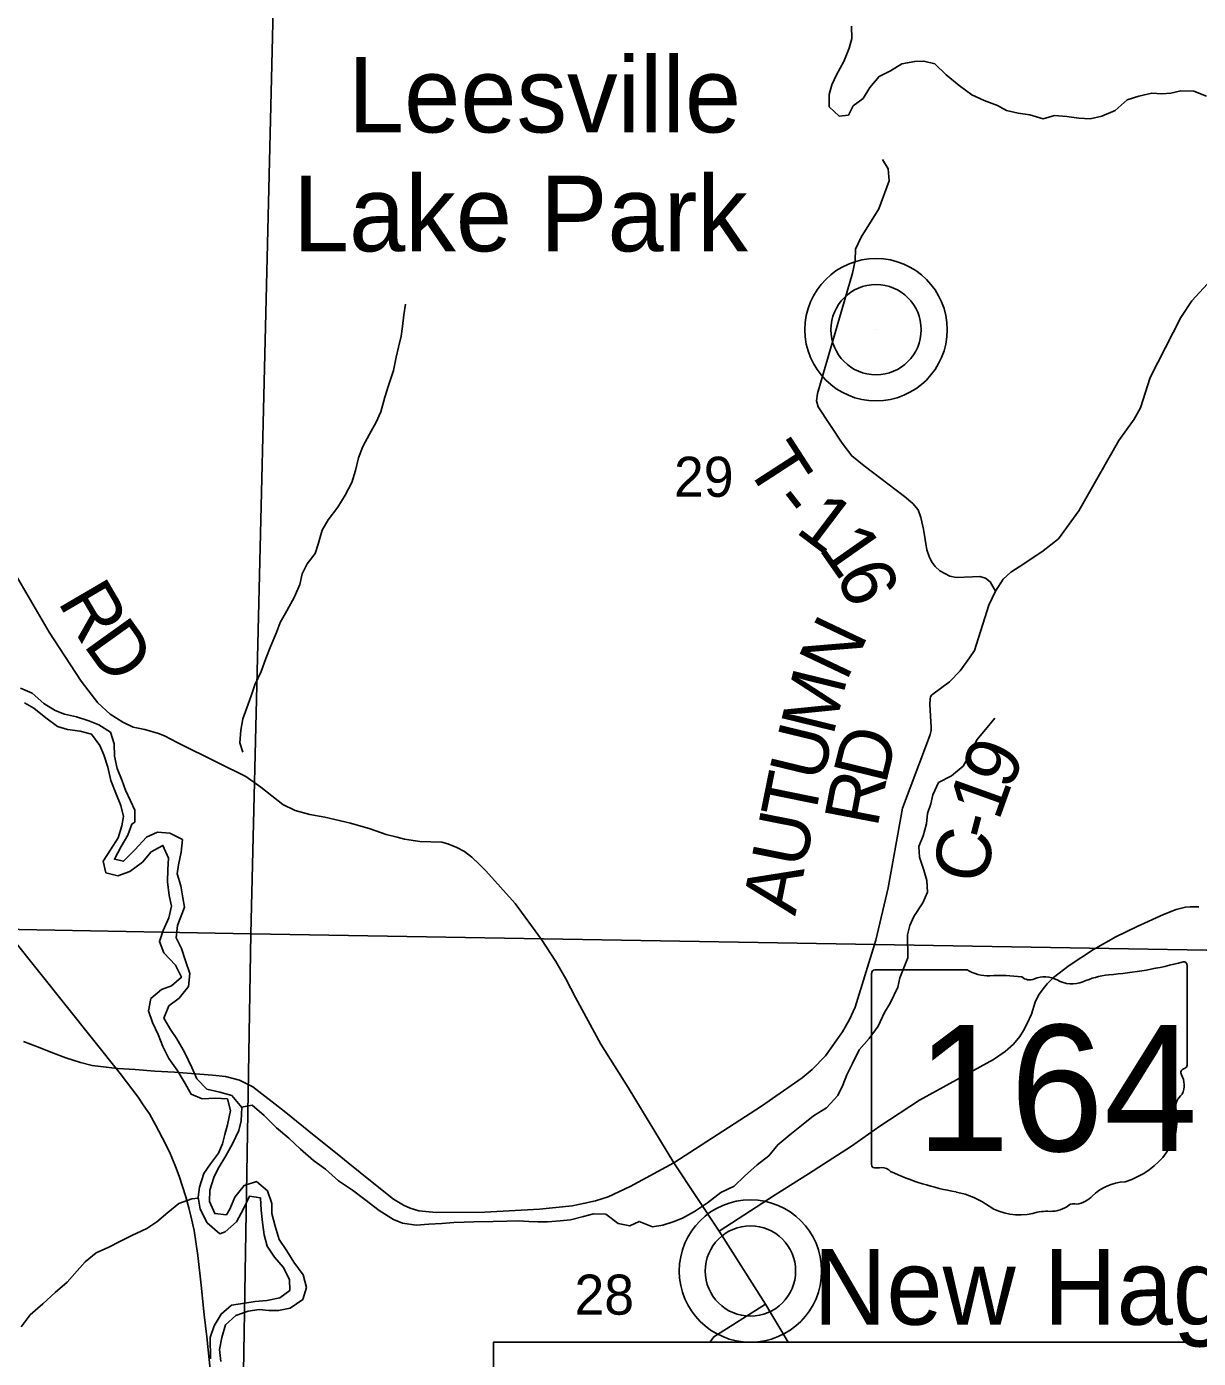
# Model space of a CAD drawing. Extents: x -1.2 to 34, y -8.5 to 22.
# Drawn here: x 6.085 to 7.31, y 18.307 to 19.699 of the extents above; entities that cross this region are included whole.
import ezdxf

# ---------------------------------------------------------------- set-up
doc = ezdxf.new("R2010")
doc.units = 0
for name, color, linetype in [('GM_X_County_Road', 7, 'Continuous'), ('GM_X_County_Road_Text', 7, 'Continuous'), ('GM_X_Major_Lake', 7, 'Continuous'), ('GM_X_Major_River', 7, 'Continuous'), ('GM_X_Minor_River', 7, 'Continuous'), ('GM_X_Rail_Line', 7, 'Continuous'), ('GM_X_Section', 7, 'Continuous'), ('GM_X_Section_Text', 7, 'Continuous'), ('GM_X_State_Location', 7, 'Continuous'), ('GM_X_State_Route', 7, 'Continuous'), ('GM_X_State_Shield', 7, 'Continuous'), ('GM_X_Township_Road', 7, 'Continuous'), ('GM_X_Township_Road_Text', 7, 'Continuous'), ('GM_X_Unincorporated', 7, 'Continuous'), ('GM_X_Unincorporated_Location', 7, 'Continuous'), ('GM_X_Unincorporated_Text', 7, 'Continuous'), ('SH_Text', 7, 'Continuous')]:
    doc.layers.add(name, color=color, linetype=linetype)

msp = doc.modelspace()

# ---------------------------------------------------------------- linework, layer by layer
at = {"layer": 'GM_X_County_Road'}
msp.add_line((6.8089, 18.4404), (6.7615, 18.5118), dxfattribs=at)
for points in [[(6.7615, 18.5118), (6.8532, 18.5707), (6.8956, 18.6004), (6.9062, 18.6093), (6.9201, 18.6236), (6.9379, 18.6486), (6.9454, 18.6613), (6.9512, 18.6743), (6.9729, 18.7443), (6.9856, 18.7989), (7.0006, 18.8824), (7.0257, 18.9486), (7.0297, 18.9593), (7.0306, 18.9635), (7.0307, 18.9669), (7.0292, 18.9904), (7.0294, 18.9965), (7.0299, 18.9985), (7.0311, 19.0002), (7.0324, 19.0015), (7.0497, 19.0144), (7.0609, 19.0256), (7.0708, 19.0394), (7.0758, 19.0471), (7.091, 19.0945), (7.0979, 19.109), (7.1059, 19.1217), (7.1138, 19.129), (7.1276, 19.1376), (7.1477, 19.1512), (7.1638, 19.1637), (7.185, 19.1929), (7.2267, 19.2664), (7.2427, 19.2887), (7.2493, 19.3006), (7.2594, 19.3323), (7.2915, 19.3948), (7.303, 19.4125), (7.388, 19.5045)], [(6.7996, 18.3243), (6.7996, 18.3245), (6.8034, 18.3297), (6.8573, 18.364), (6.8089, 18.4404)]]:
    msp.add_lwpolyline(points, dxfattribs=at)
at = {"layer": 'GM_X_Major_Lake'}
msp.add_lwpolyline([(6.9474, 19.6995), (6.9477, 19.6866), (6.9448, 19.6763), (6.9393, 19.6625), (6.9316, 19.6484), (6.9268, 19.6381), (6.9239, 19.6281), (6.9241, 19.6149), (6.9346, 19.6052), (6.9441, 19.6065), (6.9492, 19.616), (6.9594, 19.6238), (6.9664, 19.6353), (6.9761, 19.6468), (6.9881, 19.6527), (6.9998, 19.6601), (7.0134, 19.6626), (7.023, 19.6628), (7.0344, 19.6599), (7.0464, 19.6484), (7.0599, 19.6372), (7.073, 19.6276), (7.086, 19.6217), (7.0998, 19.6163), (7.1093, 19.6111), (7.1216, 19.6083), (7.1337, 19.6066), (7.1475, 19.6026), (7.1596, 19.6059), (7.1725, 19.6049), (7.1851, 19.6032), (7.1969, 19.6027), (7.209, 19.6052), (7.223, 19.6111), (7.2354, 19.6223), (7.2478, 19.6263), (7.2611, 19.6295), (7.2718, 19.6286), (7.2812, 19.6295), (7.2915, 19.6319), (7.3052, 19.6314), (7.3182, 19.6263)], dxfattribs=at)
at = {"layer": 'GM_X_Major_River'}
for points in [[(6.1983, 18.8675), (6.1981, 18.88), (6.1938, 18.8898), (6.1886, 18.9011), (6.1851, 18.9109), (6.1799, 18.9238), (6.177, 18.9366), (6.1768, 18.9495), (6.1728, 18.9616), (6.1605, 18.9694), (6.1502, 18.9734), (6.1372, 18.9777), (6.1246, 18.9805), (6.115, 18.9842), (6.1031, 18.9916), (6.0908, 19.0024), (6.0789, 19.0075)], [(6.083, 18.9924), (6.0926, 18.9868), (6.1053, 18.9768), (6.1176, 18.9675), (6.1279, 18.9643), (6.1412, 18.9626), (6.1531, 18.9594), (6.1616, 18.9477), (6.166, 18.938), (6.17, 18.9251), (6.1733, 18.9111), (6.1784, 18.8979), (6.1836, 18.8851), (6.1864, 18.8734), (6.1847, 18.8639), (6.1807, 18.8513), (6.1729, 18.8386), (6.1652, 18.8267), (6.168, 18.8146), (6.1806, 18.8114), (6.1931, 18.8162), (6.2062, 18.8259), (6.2152, 18.8367), (6.2276, 18.8433), (6.2335, 18.8301), (6.2326, 18.818), (6.2324, 18.8051), (6.2342, 18.7911), (6.2366, 18.7797), (6.2338, 18.7675), (6.2279, 18.7545), (6.2239, 18.7431), (6.2287, 18.731), (6.2407, 18.7183), (6.247, 18.7055), (6.2365, 18.6966), (6.2263, 18.6926), (6.215, 18.6833), (6.2126, 18.6704), (6.2166, 18.6583), (6.2225, 18.6459), (6.2276, 18.6331), (6.2339, 18.6207), (6.2425, 18.6086), (6.2499, 18.5962), (6.257, 18.5835), (6.2688, 18.5787), (6.2825, 18.5793), (6.2951, 18.5784), (6.2983, 18.5663), (6.2951, 18.5514), (6.2923, 18.5412), (6.2898, 18.5316), (6.2857, 18.5217), (6.2772, 18.5105), (6.2705, 18.5006)], [(6.294, 18.4573), (6.2818, 18.4586), (6.2763, 18.4714), (6.2765, 18.4832), (6.2808, 18.4962), (6.2852, 18.5057), (6.2934, 18.5188), (6.3004, 18.5314), (6.307, 18.5456), (6.3095, 18.5555), (6.31, 18.5695), (6.2996, 18.5819), (6.287, 18.5855), (6.2736, 18.5887), (6.2632, 18.5995), (6.2577, 18.6112), (6.2502, 18.6274), (6.242, 18.6413), (6.2357, 18.651), (6.2287, 18.6627), (6.2338, 18.6757), (6.2447, 18.6838), (6.2544, 18.6958), (6.2557, 18.7094), (6.2513, 18.7227), (6.2472, 18.7355), (6.2414, 18.7468), (6.243, 18.7597), (6.2503, 18.7788), (6.2483, 18.7886), (6.2462, 18.8011), (6.2425, 18.8136), (6.2439, 18.8231), (6.2467, 18.8361), (6.248, 18.8494), (6.235, 18.856), (6.2221, 18.8573), (6.2104, 18.8518), (6.1984, 18.8387), (6.1864, 18.8267), (6.1769, 18.8288), (6.1839, 18.8422), (6.1909, 18.8541), (6.1953, 18.8656), (6.1983, 18.8675)], [(6.2705, 18.5006), (6.2658, 18.4861), (6.2644, 18.4758), (6.2665, 18.4633), (6.274, 18.449), (6.2871, 18.4374)], [(6.2882, 18.3039), (6.2868, 18.3167), (6.2893, 18.3293), (6.2929, 18.3423), (6.3037, 18.3523), (6.3166, 18.3567), (6.3283, 18.3584), (6.3382, 18.3574), (6.3485, 18.3572), (6.3606, 18.3597), (6.3738, 18.369), (6.3777, 18.3813), (6.3741, 18.3945), (6.3644, 18.408), (6.357, 18.4196), (6.3492, 18.4316), (6.3448, 18.4456), (6.3415, 18.4588), (6.3413, 18.4691), (6.3369, 18.4823), (6.3254, 18.492), (6.3125, 18.488), (6.3028, 18.4757), (6.2977, 18.4631), (6.294, 18.4573)], [(6.2871, 18.4374), (6.2928, 18.4394), (6.3044, 18.4499), (6.3118, 18.4637), (6.318, 18.4767), (6.3295, 18.475), (6.3304, 18.4621), (6.3318, 18.4492), (6.3335, 18.4363), (6.3367, 18.4246), (6.3442, 18.413), (6.3534, 18.4025), (6.3601, 18.3897), (6.3603, 18.3783), (6.3498, 18.3705), (6.3362, 18.3677), (6.324, 18.3667), (6.3134, 18.365), (6.2994, 18.3629), (6.2885, 18.3536), (6.2811, 18.3413), (6.2771, 18.3291), (6.2775, 18.3067)]]:
    msp.add_lwpolyline(points, dxfattribs=at)
at = {"layer": 'GM_X_Minor_River'}
for points in [[(6.311, 18.9407), (6.3079, 18.9506), (6.3089, 18.9638), (6.3111, 18.9756), (6.3152, 18.987), (6.32, 18.9996), (6.3237, 19.011), (6.3304, 19.0251), (6.3352, 19.0388), (6.3405, 19.0518), (6.3464, 19.0659), (6.3501, 19.0761), (6.3572, 19.0883), (6.3651, 19.1032), (6.3707, 19.1158), (6.3732, 19.1272), (6.3785, 19.1375), (6.3867, 19.1482), (6.39, 19.1581), (6.3941, 19.1729), (6.4005, 19.1836), (6.4106, 19.1966), (6.4181, 19.2092), (6.4252, 19.2225), (6.4289, 19.2351), (6.4322, 19.2484), (6.4366, 19.2602), (6.4437, 19.2731), (6.4505, 19.2857), (6.4553, 19.2964), (6.4597, 19.3116), (6.4634, 19.3238), (6.4686, 19.3397), (6.4715, 19.3534), (6.4737, 19.3641), (6.4767, 19.3755), (6.4781, 19.3854), (6.4795, 19.3979), (6.4813, 19.4089)], [(6.3099, 18.5697), (6.321, 18.5719), (6.3333, 18.561), (6.3463, 18.5482), (6.3593, 18.5373), (6.3715, 18.526), (6.3849, 18.514), (6.3976, 18.505), (6.4113, 18.4929), (6.4258, 18.4832), (6.4388, 18.4734), (6.4538, 18.4618), (6.4686, 18.4524), (6.4782, 18.4487), (6.4922, 18.4465), (6.5055, 18.4474), (6.5192, 18.4483), (6.5317, 18.4492), (6.5424, 18.4496), (6.5526, 18.4501), (6.5727, 18.4503), (6.5872, 18.4508), (6.5989, 18.4509), (6.61, 18.4502), (6.6195, 18.4499), (6.6297, 18.45), (6.643, 18.4512), (6.6536, 18.4521), (6.6673, 18.4556), (6.6775, 18.4584), (6.6904, 18.4581), (6.7034, 18.4483), (6.7156, 18.4458), (6.7254, 18.4504), (6.7395, 18.4448), (6.7502, 18.4465), (6.7608, 18.45), (6.7706, 18.4538), (6.7831, 18.4608), (6.7967, 18.47), (6.8106, 18.4807), (6.8246, 18.4873), (6.8356, 18.4977), (6.8488, 18.5095), (6.8608, 18.5191), (6.8702, 18.5306), (6.883, 18.541), (6.8951, 18.5505), (6.9076, 18.5609), (6.9212, 18.569), (6.9332, 18.582), (6.9384, 18.5927), (6.9425, 18.6037), (6.9485, 18.6155), (6.9552, 18.6296), (6.9658, 18.6415), (6.9751, 18.6545), (6.9819, 18.6689), (6.9879, 18.6785), (6.9957, 18.6953), (6.9979, 18.7048), (7.0061, 18.7257), (7.0059, 18.75), (7.0084, 18.7595), (7.0125, 18.769), (7.0219, 18.7832), (7.0267, 18.7946), (7.0259, 18.8067), (7.0228, 18.8173), (7.0185, 18.8309), (7.0176, 18.8423), (7.0221, 18.8534), (7.0258, 18.8659), (7.0268, 18.8766), (7.0301, 18.8868), (7.0323, 18.8963), (7.0383, 18.9089), (7.0519, 18.9162), (7.064, 18.9262), (7.073, 18.9422), (7.0782, 18.9537), (7.0891, 18.9667), (7.097, 18.9762)], [(6.2646, 18.4746), (6.2577, 18.4742), (6.2444, 18.4691), (6.2327, 18.4599), (6.2214, 18.4499), (6.2108, 18.443), (6.1953, 18.4357), (6.1825, 18.4295), (6.1711, 18.4237), (6.1579, 18.4175), (6.1462, 18.4083), (6.1379, 18.3988), (6.1277, 18.3869), (6.1149, 18.3762), (6.1021, 18.3643), (6.0889, 18.3528), (6.0795, 18.3402)]]:
    msp.add_lwpolyline(points, dxfattribs=at)
at = {"layer": 'GM_X_Rail_Line'}
msp.add_lwpolyline([(6.2878, 18.1907), (6.2734, 18.3297), (6.2708, 18.353), (6.2677, 18.3839), (6.2642, 18.4149), (6.2622, 18.4291), (6.2602, 18.4409), (6.2576, 18.453), (6.2548, 18.4645), (6.2517, 18.4762), (6.2482, 18.4869), (6.2446, 18.4978), (6.2408, 18.508), (6.2344, 18.523), (6.227, 18.5381), (6.2199, 18.5512), (6.2135, 18.5627), (6.2077, 18.5713), (6.2019, 18.5801), (6.1831, 18.605), (6.07, 18.7464)], dxfattribs=at)
at = {"layer": 'GM_X_Section'}
for points in [[(5.4939, 19.7699), (6.3436, 19.7459), (6.3194, 18.751), (5.4804, 18.7665), (5.4956, 19.6725)], [(6.3436, 19.7459), (7.3559, 19.7295), (7.3389, 18.7336), (6.3194, 18.751)], [(5.4804, 18.7665), (6.3194, 18.751), (6.3024, 17.731), (5.4646, 17.7402), (5.479, 18.6512)]]:
    msp.add_lwpolyline(points, close=True, dxfattribs=at)
msp.add_lwpolyline([(6.5688, 17.7257), (6.3024, 17.731), (6.3194, 18.751), (7.3389, 18.7336), (7.3297, 18.3243)], dxfattribs=at)
at = {"layer": 'GM_X_State_Route'}
msp.add_line((6.7615, 18.5118), (6.8089, 18.4404), dxfattribs=at)
for points in [[(6.8089, 18.4404), (6.8675, 18.4781), (6.9023, 18.5002), (6.9181, 18.5104), (6.9474, 18.5291), (6.977, 18.5501), (7.0184, 18.5773), (7.0362, 18.5868), (7.0959, 18.6198), (7.108, 18.628), (7.1165, 18.6358), (7.1232, 18.6436), (7.1271, 18.65), (7.1311, 18.6572), (7.1353, 18.6671), (7.1392, 18.6796), (7.1427, 18.6868), (7.1475, 18.6936), (7.1517, 18.6987), (7.1586, 18.7052), (7.1749, 18.7178), (7.2002, 18.7347), (7.2235, 18.7479), (7.2459, 18.7587), (7.2733, 18.7712), (7.2867, 18.7763), (7.2963, 18.7788), (7.3012, 18.779), (7.3102, 18.7793)], [(6.0819, 18.6384), (6.0964, 18.6327), (6.1134, 18.6261), (6.1261, 18.6212), (6.1414, 18.6166), (6.1536, 18.6135), (6.1683, 18.6116), (6.1801, 18.6101), (6.1985, 18.6091), (6.2192, 18.6074), (6.2396, 18.6064), (6.2793, 18.6031), (6.2932, 18.6017), (6.3075, 18.598), (6.3217, 18.5912), (6.3544, 18.5658), (6.3875, 18.5388), (6.4097, 18.5212), (6.4212, 18.5116), (6.4465, 18.4916), (6.4688, 18.4738), (6.4792, 18.4675), (6.4862, 18.4643), (6.4952, 18.4614), (6.5131, 18.4598), (6.564, 18.4601), (6.6211, 18.4633), (6.6554, 18.4668), (6.6687, 18.4694), (6.6798, 18.4719), (6.6929, 18.4761), (6.716, 18.4868), (6.7615, 18.5118)]]:
    msp.add_lwpolyline(points, dxfattribs=at)
at = {"layer": 'GM_X_State_Shield'}
for p, q in [((7.298, 18.6137), (7.298, 18.7184)), ((6.9684, 18.71), (6.9684, 18.5098)), ((7.0682, 18.7134), (6.9717, 18.7134)), ((7.298, 18.6137), (7.298, 18.6137))]:
    msp.add_line(p, q, dxfattribs=at)
for centre, major_axis, start_param, end_param in [((7.1806, 18.9862), (0.3495, 0), 4.814394, 5.042369), ((7.2943, 18.7188), (0.00367, 0), 6.141152, 7.989035), ((6.9722, 18.7104), (0.00382, 0), 1.712693, 3.28349), ((7.0912, 18.7366), (0.037, 0), 4.042523, 4.731795), ((7.1034, 18.601), (0.133, 0), 1.404758, 1.657858), ((7.1336, 18.7114), (0.0107, 0), 3.836095, 5.185415), ((7.1493, 18.6883), (0.0222, 0), 0.950623, 2.079405), ((7.178, 18.72), (0.0267, 0), 4.081561, 5.145723), ((7.2252, 18.6523), (0.0703, 0), 1.699011, 2.107814), ((7.2972, 18.606), (0.00568, 0), 1.883978, 3.671073), ((7.2941, 18.6133), (0.00393, 0), 5.05454, 6.418171), ((7.261, 18.5928), (0.0341, 0), 5.934695, 6.695948), ((7.3111, 18.5699), (0.0248, 0), 2.387724, 3.262537), ((7.2002, 18.5565), (0.0874, 0), 5.101752, 6.440018), ((6.9722, 18.5094), (0.00385, 0), 3.00124, 4.508301), ((6.9728, 18.5299), (0.0294, 0), 4.665946, 4.897461), ((6.9788, 18.4983), (0.0106, 0), 0.519207, 1.627899), ((7.1127, 18.6781), (0.2524, 0), 4.195997, 4.488961), ((7.0374, 18.4199), (0.079, 0), 0.823519, 1.323587), ((7.237, 18.4537), (0.0479, 0), 1.647645, 2.488434), ((7.1228, 18.4973), (0.0501, 0), 4.026481, 4.996735), ((7.1554, 18.4823), (0.0267, 0), 4.691044, 5.507374), ((7.1796, 18.4629), (0.00752, 0), 1.147584, 2.315152), ((7.1764, 18.4904), (0.0282, 0), 4.937069, 5.64225), ((7.1518, 18.4281), (0.0412, 0), 1.495662, 1.94098)]:
    msp.add_ellipse(centre, major_axis=major_axis, ratio=0.8, start_param=start_param, end_param=end_param, dxfattribs=at)
at = {"layer": 'GM_X_Township_Road'}
msp.add_line((6.8573, 18.364), (6.8812, 18.3243), dxfattribs=at)
for points in [[(6.9796, 19.56), (6.9858, 19.5502), (6.9868, 19.5377), (6.9759, 19.5086), (6.9574, 19.479), (6.9515, 19.4664), (6.9513, 19.4546), (6.9485, 19.4413), (6.9118, 19.3156), (6.9108, 19.308), (6.9125, 19.3016), (6.9377, 19.2638), (6.9476, 19.2503), (6.9606, 19.2401), (7.0027, 19.2078), (7.0113, 19.2005), (7.017, 19.1939), (7.0198, 19.1858), (7.0227, 19.1739), (7.0261, 19.1522), (7.0289, 19.1441), (7.0316, 19.1391), (7.0348, 19.1348), (7.0398, 19.1304), (7.0449, 19.1273), (7.0502, 19.1248), (7.0569, 19.1233), (7.0738, 19.124), (7.0813, 19.1242), (7.0875, 19.1225), (7.0922, 19.1186), (7.0979, 19.109)], [(6.0673, 19.1373), (6.1087, 19.0662), (6.1421, 19.015), (6.1597, 18.9922), (6.1724, 18.9804), (6.1856, 18.972), (6.1966, 18.9669), (6.2088, 18.9645), (6.2231, 18.9604), (6.2293, 18.9578), (6.2425, 18.9509), (6.2852, 18.9295), (6.3143, 18.9155), (6.3298, 18.9042), (6.353, 18.8861), (6.3659, 18.8797), (6.3811, 18.8758), (6.3968, 18.873), (6.4237, 18.8665), (6.4441, 18.8606), (6.4611, 18.8549), (6.4724, 18.8521), (6.4803, 18.85), (6.4962, 18.8474), (6.5193, 18.8466), (6.5253, 18.8451), (6.5349, 18.841), (6.5429, 18.837), (6.5505, 18.831), (6.5581, 18.8237), (6.5651, 18.8167), (6.5957, 18.7828), (6.6234, 18.7451), (6.6384, 18.7219), (6.6487, 18.7039), (6.6589, 18.6843), (6.6855, 18.6357), (6.7138, 18.5902), (6.7615, 18.5118)]]:
    msp.add_lwpolyline(points, dxfattribs=at)
at = {"layer": 'GM_X_Unincorporated'}
for centre, radius in [((6.973, 19.3822), 0.0744), ((6.973, 19.3822), 0.0472), ((6.8417, 18.3986), 0.0744), ((6.8417, 18.3986), 0.0472)]:
    msp.add_circle(centre, radius, dxfattribs=at)
at = {"layer": 'GM_X_Unincorporated_Location'}
for p, q in [((6.973, 19.3822), (6.973, 19.3822)), ((6.8417, 18.3986), (6.8417, 18.3986))]:
    msp.add_line(p, q, dxfattribs=at)
at = {"layer": 'SH_Text'}
msp.add_lwpolyline([(6.5732, 17.8243), (6.5732, 18.3243), (8.2113, 18.3243), (8.2113, 17.8243), (6.7063, 17.8243)], dxfattribs=at)

# ---------------------------------------------------------------- texts
at = {"layer": 'GM_X_County_Road_Text'}
for s, rotation, p in [('N', 64.6063, (6.9418, 19.0137)), ('M', 76.2281, (6.9281, 18.9567)), ('U', 76.383, (6.9163, 18.9081)), ('D', 76.2553, (6.983, 18.9059)), ('9', 66.4608, (7.1126, 18.8998)), ('T', 78.5148, (6.908, 18.867)), ('R', 79.1355, (6.9743, 18.8608)), ('1', 70.2583, (7.1011, 18.8678)), ('U', 78.7554, (6.8983, 18.8181)), ('-', 75.3371, (7.0956, 18.8465)), ('C', 79.6477, (7.0875, 18.8017)), ('A', 78.7554, (6.8885, 18.769))]:
    msp.add_text(s, height=0.0568, rotation=rotation, dxfattribs=at).set_placement(p)
at = {"layer": 'GM_X_Section_Text'}
for s, p in [('29', (6.7618, 19.2076)), ('28', (6.6578, 18.353))]:
    msp.add_text(s, height=0.04186, rotation=0, dxfattribs=at).set_placement(p)
at = {"layer": 'GM_X_State_Location'}
for s in ['s', 'r']:
    msp.add_text(s, height=0.000189, dxfattribs=at).set_placement((7.1295, 18.5966))
msp.add_text('164', height=0.000189, rotation=0, dxfattribs=at).set_placement((7.0626, 18.5828))
at = {"layer": 'GM_X_State_Shield'}
msp.add_text('164', height=0.13184, dxfattribs=at).set_placement((7.0149, 18.5239))
at = {"layer": 'GM_X_Township_Road_Text'}
for s, rotation, p in [('T', 302.9674, (6.8354, 19.241)), ('-', 308.0466, (6.8617, 19.2009)), ('1', 322.8642, (6.8875, 19.1713)), ('1', 305.0383, (6.9122, 19.1535)), ('6', 291.6333, (6.9306, 19.128)), ('R', 300.3205, (6.117, 19.098)), ('D', 305.6153, (6.1436, 19.053))]:
    msp.add_text(s, height=0.0568, rotation=rotation, dxfattribs=at).set_placement(p)
at = {"layer": 'GM_X_Unincorporated_Text'}
for s, height, p in [('Leesville', 0.07898, (6.421, 19.5883)), ('Lake Park', 0.07898, (6.3635, 19.4641)), ('New Hagerstown', 0.078977, (6.9076, 18.3425))]:
    msp.add_text(s, height=height, rotation=0, dxfattribs=at).set_placement(p)

doc.saveas('drawing.dxf')
